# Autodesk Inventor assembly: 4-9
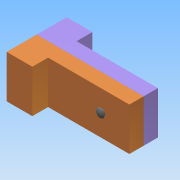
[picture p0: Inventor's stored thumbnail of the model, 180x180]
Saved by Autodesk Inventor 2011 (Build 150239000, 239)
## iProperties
Created: 2014-03
Part Number: 4-9
Document SubType Name: Assembly
Designer: Administrator
Author: Administrator
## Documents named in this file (3)
- J:\新作模型\4-9.iam
- J:\新作模型\4-9a.ipt
- J:\新作模型\4-9锥形销 GB_T 117 A 6 x 22.ipt
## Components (3 placed, 2 different names)
1. 4-9a:1 — 配合:1, 表面齐平:1, 表面齐平:2, 配合:2, 配合:3
2. 4-9a:2 — 配合:1, 表面齐平:1, 表面齐平:2
3. 4-9锥形销 GB_T 117 A 6 x 22:1 — 配合:2, 配合:3
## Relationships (5: Mate 3, Flush 2)
- 配合:1 [Mate]: 4-9a:1 ↔ 4-9a:2
- 表面齐平:1 [Flush]: 4-9a:1 ↔ 4-9a:2
- 表面齐平:2 [Flush]: 4-9a:1 ↔ 4-9a:2
- 配合:2 [Mate]: 4-9a:1 ↔ 4-9锥形销 GB_T 117 A 6 x 22:1
- 配合:3 [Mate]: 4-9a:1 ↔ 4-9锥形销 GB_T 117 A 6 x 22:1
